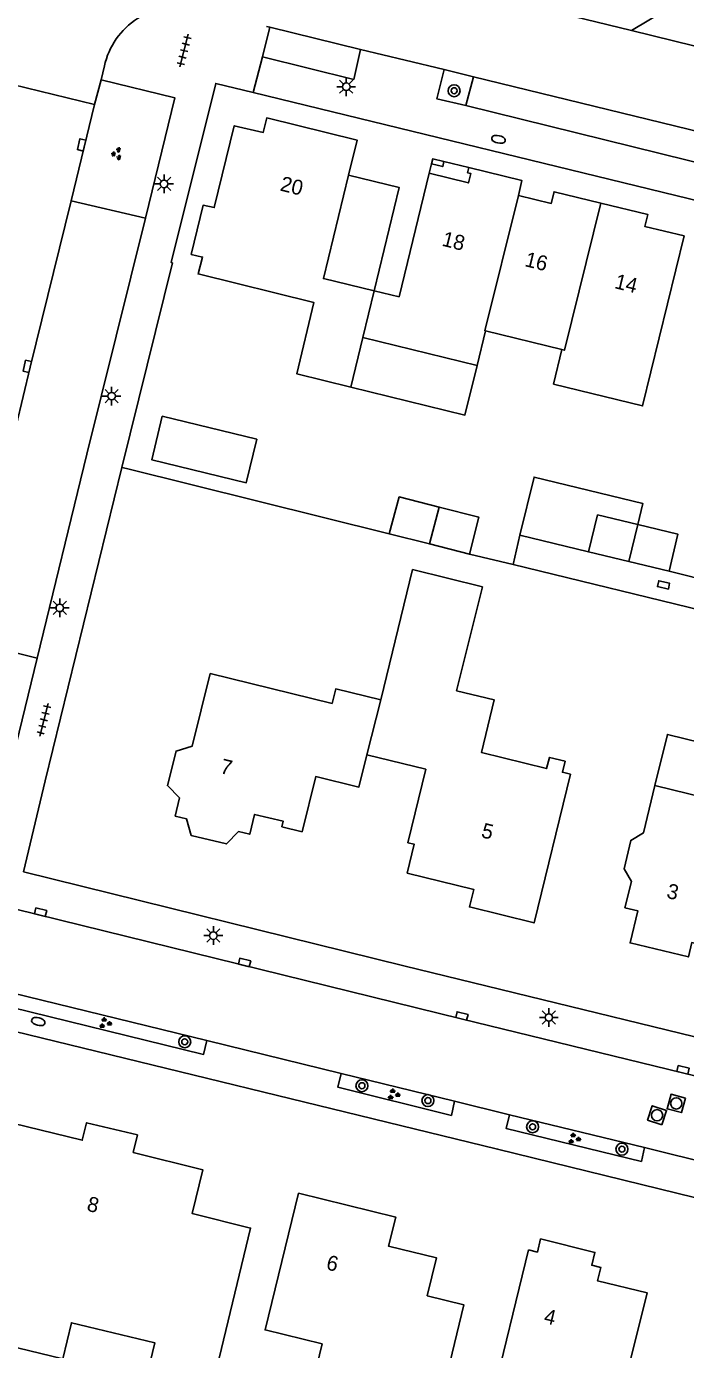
# Model space of a CAD drawing. Extents: x 125000 to 129004, y 397500 to 399008.
# Drawn here: x 126718 to 126762, y 398005.2 to 398093.6 of the extents above; entities that cross this region are included whole.
import ezdxf

# ---------------------------------------------------------------- set-up
doc = ezdxf.new("R2010")
doc.units = 0
for name, color, linetype in [('gg-afsc-erfafscheiding', 7, 'Continuous'), ('gg-afsc-muur', 7, 'Continuous'), ('gg-anno-huisnummerreeks BGT', 7, 'Continuous'), ('gg-bbg-bijgebouw', 7, 'Continuous'), ('gg-bbg-gedigitaliseerde bebouwing', 7, 'Continuous'), ('gg-bbg-hoofdgebouw', 7, 'Continuous'), ('gg-bbg-luifel en loopbrug', 7, 'Continuous'), ('gg-bbg-onder overbouw', 7, 'Continuous'), ('gg-bbg-pand overbouw', 7, 'Continuous'), ('gg-bbg-pilaar onder overbouw', 7, 'Continuous'), ('gg-bbg-pilaar pand', 7, 'Continuous'), ('gg-bbg-tussenscheiding', 7, 'Continuous'), ('gg-knt-verharding', 7, 'Continuous'), ('gg-knt-verharding nz', 7, 'Continuous'), ('gt-grn-weggrens', 7, 'Continuous'), ('gt-symb-boom', 7, 'Continuous'), ('gt-symb-brandkraan', 7, 'Continuous'), ('gt-symb-groenvak', 7, 'Continuous'), ('gt-symb-kolk', 7, 'Continuous'), ('gt-symb-kolk center center', 7, 'Continuous'), ('gt-symb-lichtmast', 7, 'Continuous'), ('gt-symb-rioolschacht', 7, 'Continuous'), ('gt-symb-tegel verharding', 7, 'Continuous')]:
    doc.layers.add(name, color=color, linetype=linetype)

# ---------------------------------------------------------------- blocks, each defined once
blk = doc.blocks.new('gt0-LMAST')
at = {"layer": 'gt-symb-lichtmast'}
for p, q in [((-0.182, 0.173), (-0.447, 0.438)), ((-0.005, 0.246), (-0.005, 0.621)), ((0.172, 0.173), (0.437, 0.438)), ((-0.255, -0.004), (-0.63, -0.004)), ((-0.182, -0.181), (-0.447, -0.446)), ((-0.005, -0.254), (-0.005, -0.629)), ((0.437, -0.446), (0.172, -0.181)), ((0.245, -0.004), (0.62, -0.004))]:
    blk.add_line(p, q, dxfattribs=at)
blk.add_circle((-0.005, -0.004), 0.25, dxfattribs=at)
blk = doc.blocks.new('gt0-TEG1')
at = {"layer": 'gt-symb-tegel verharding'}
for p, q in [((-1.125, 0), (1.125, 0)), ((-0.9, -0.25), (-0.9, 0.25)), ((-0.45, -0.25), (-0.45, 0.25)), ((0, -0.25), (0, 0.25)), ((0.45, -0.25), (0.45, 0.25)), ((0.9, -0.25), (0.9, 0.25))]:
    blk.add_line(p, q, dxfattribs=at)
blk = doc.blocks.new('gt0-BOOM')
at = {"layer": 'gt-symb-boom'}
for radius in [0.4, 0.2]:
    blk.add_circle((0, 0), radius, dxfattribs=at)
blk = doc.blocks.new('gt0-BR')
at = {"layer": 'gt-symb-brandkraan'}
for centre, radius, start, end in [((-0.244, 0), 0.206, 107.56694, 252.43307), ((0.599, -2.664), 3, 106.89205, 107.56694), ((0, -0.691), 0.938, 73.10799, 106.89205), ((-0.599, -2.664), 3, 72.43309, 73.10799), ((0.244, 0), 0.206, 287.56695, 72.43309), ((0.599, 2.664), 3, 252.43307, 253.10797), ((0, 0.691), 0.938, 253.10797, 286.89206), ((-0.599, 2.664), 3, 286.89206, 287.56695)]:
    blk.add_arc(centre, radius, start, end, dxfattribs=at)
blk = doc.blocks.new('gt0-GRVAK')
at = {"layer": 'gt-symb-groenvak'}
for p, q in [((-0.11, 0.189), (-0.228, 0.24)), ((-0.182, 0.153), (0.088, 0.153)), ((-0.091, 0.211), (-0.156, 0.322)), ((-0.047, 0.214), (-0.047, 0.393)), ((-0.004, 0.211), (0.061, 0.322)), ((0.015, 0.189), (0.133, 0.24)), ((0.262, -0.052), (0.197, 0.059)), ((0.305, -0.049), (0.305, 0.13)), ((0.349, -0.052), (0.414, 0.059)), ((-0.245, -0.228), (-0.363, -0.177)), ((-0.318, -0.264), (-0.047, -0.264)), ((-0.226, -0.206), (-0.291, -0.095)), ((-0.183, -0.203), (-0.183, -0.024)), ((-0.139, -0.206), (-0.074, -0.095)), ((-0.12, -0.228), (-0.002, -0.177)), ((0.243, -0.074), (0.125, -0.023)), ((0.17, -0.11), (0.441, -0.11)), ((0.368, -0.074), (0.486, -0.023))]:
    blk.add_line(p, q, dxfattribs=at)
blk = doc.blocks.new('gt0-KOLK')
at = {"layer": 'gt-symb-kolk'}
blk.add_lwpolyline([(0, 0), (0.375, 0), (0.375, 0.4), (-0.375, 0.4), (-0.375, 0), (0, 0)], dxfattribs=at)
blk = doc.blocks.new('gt0-KOLKCC')
at = {"layer": 'gt-symb-kolk center center'}
blk.add_lwpolyline([(-0.375, 0.2), (0.375, 0.2), (0.375, -0.2), (-0.375, -0.2)], close=True, dxfattribs=at)
blk = doc.blocks.new('gt0-RS')
at = {"layer": 'gt-symb-rioolschacht'}
blk.add_lwpolyline([(-0.5, -0.5), (0.5, -0.5), (0.5, 0.5), (-0.5, 0.5)], close=True, dxfattribs=at)
blk.add_circle((0, 0), 0.375, dxfattribs=at)

msp = doc.modelspace()

# ---------------------------------------------------------------- linework, layer by layer
at = {"layer": 'gg-afsc-erfafscheiding'}
for p, q in [((126724.351, 398064.121), (126719.221, 398043.177)), ((126742.224, 398059.684), (126724.663, 398064.05)), ((126750.494, 398057.621), (126750.952, 398059.587)), ((126747.589, 398058.33), (126750.494, 398057.621)), ((126760.922, 398057.186), (126768.349, 398055.337))]:
    msp.add_line(p, q, dxfattribs=at)
at = {"layer": 'gg-afsc-muur'}
for p, q in [((126727.738, 398077.785), (126724.351, 398064.121)), ((126724.351, 398064.121), (126724.663, 398064.05))]:
    msp.add_line(p, q, dxfattribs=at)
at = {"layer": 'gg-bbg-bijgebouw'}
for p, q in [((126742.224, 398059.684), (126744.907, 398059.007)), ((126744.907, 398059.007), (126747.589, 398058.33)), ((126755.532, 398058.478), (126758.227, 398057.832)), ((126758.227, 398057.832), (126760.922, 398057.186))]:
    msp.add_line(p, q, dxfattribs=at)
for points in [[(126733.358, 398066.01), (126727.052, 398067.534), (126726.357, 398064.622), (126732.663, 398063.097), (126733.358, 398066.01)], [(126745.547, 398061.47), (126742.882, 398062.147), (126742.224, 398059.684)], [(126747.589, 398058.33), (126748.211, 398060.792), (126745.547, 398061.47)], [(126758.83, 398060.296), (126756.148, 398060.945), (126755.532, 398058.478)], [(126760.922, 398057.186), (126761.512, 398059.646), (126758.83, 398060.296)]]:
    msp.add_lwpolyline(points, dxfattribs=at)
at = {"layer": 'gg-bbg-gedigitaliseerde bebouwing'}
msp.add_lwpolyline([(126744.727, 398002.6), (126743.485, 397997.447), (126736.193, 397999.205), (126737.725, 398005.556)], dxfattribs=at)
at = {"layer": 'gg-bbg-hoofdgebouw'}
for p, q in [((126744.89, 398083.768), (126742.883, 398075.504)), ((126741.212, 398075.91), (126740.455, 398072.798)), ((126741.212, 398075.91), (126742.883, 398075.504)), ((126740.455, 398072.798), (126739.648, 398069.477)), ((126740.455, 398072.798), (126748.087, 398070.933)), ((126748.087, 398070.933), (126748.653, 398073.243)), ((126748.653, 398073.243), (126753.748, 398071.993)), ((126753.748, 398071.993), (126753.196, 398069.678))]:
    msp.add_line(p, q, dxfattribs=at)
for points in [[(126739.648, 398069.477), (126736.034, 398070.376), (126737.184, 398075.133), (126729.447, 398077.043), (126729.74, 398078.17), (126728.981, 398078.352), (126729.773, 398081.639), (126730.522, 398081.476), (126731.862, 398086.947), (126733.794, 398086.503), (126734.03, 398087.464), (126740.069, 398085.985), (126739.497, 398083.634)], [(126750.86, 398082.296), (126751.091, 398083.279), (126747.537, 398084.149)], [(126739.497, 398083.634), (126737.82, 398076.734), (126741.212, 398075.91)], [(126756.37, 398081.772), (126753.235, 398082.538), (126753.045, 398081.761), (126750.86, 398082.296)], [(126753.196, 398069.678), (126759.155, 398068.227), (126761.921, 398079.582), (126759.3, 398080.222), (126759.504, 398081.005), (126756.37, 398081.772)], [(126741.651, 398048.586), (126743.778, 398057.295), (126748.446, 398056.134), (126746.719, 398049.191), (126749.237, 398048.587), (126748.392, 398045.066), (126752.739, 398043.992), (126752.921, 398044.74), (126753.97, 398044.484), (126753.79, 398043.746), (126754.324, 398043.615), (126751.898, 398033.677), (126747.58, 398034.756), (126747.871, 398035.92), (126743.42, 398037.013), (126743.893, 398038.936), (126743.466, 398039.041), (126744.657, 398043.953), (126740.716, 398044.909)], [(126759.972, 398042.859), (126759.202, 398039.699), (126758.365, 398039.198), (126757.91, 398037.293), (126758.403, 398036.445), (126757.974, 398034.691), (126758.839, 398034.48), (126758.313, 398032.341), (126762.21, 398031.407), (126762.441, 398032.37), (126766.753, 398031.297), (126768.875, 398039.997), (126772.277, 398039.167), (126775.303, 398051.571), (126771.055, 398052.607), (126769.034, 398044.256), (126766.363, 398044.913)], [(126730.245, 398050.341), (126729.047, 398045.496), (126727.967, 398045.166), (126727.392, 398042.853), (126728.198, 398042.03), (126727.915, 398040.824), (126728.665, 398040.647), (126728.987, 398039.534), (126731.335, 398038.965), (126732.145, 398039.783), (126732.894, 398039.602), (126733.216, 398040.933), (126735.131, 398040.47), (126735.04, 398040.111), (126736.406, 398039.766)], [(126741.651, 398048.586), (126738.638, 398049.321), (126738.4, 398048.349), (126730.245, 398050.341)], [(126736.406, 398039.766), (126737.303, 398043.465), (126740.196, 398042.763), (126740.716, 398044.909)], [(126766.363, 398044.913), (126765.522, 398041.495), (126759.972, 398042.859)], [(126720.396, 398004.551), (126713.594, 398006.203), (126714.661, 398010.595), (126713.699, 398010.829), (126714.809, 398015.395), (126715.78, 398015.159), (126717.031, 398020.309), (126721.7, 398019.166), (126721.985, 398020.331), (126725.392, 398019.515), (126725.113, 398018.348), (126729.767, 398017.181), (126729.037, 398014.271), (126732.956, 398013.288), (126729.653, 397999.601)], [(126737.725, 398005.556), (126733.918, 398006.483), (126736.143, 398015.621)], [(126736.143, 398015.621), (126742.653, 398014.025), (126742.177, 398012.082), (126745.382, 398011.296), (126744.762, 398008.771), (126747.202, 398008.175), (126745.796, 398002.342), (126744.727, 398002.6)], [(126751.516, 398011.834), (126752.117, 398011.691), (126752.333, 398012.564), (126755.965, 398011.667), (126755.757, 398010.808), (126756.367, 398010.65), (126756.138, 398009.767), (126759.457, 398008.975), (126757.897, 398002.709), (126761.037, 398001.918), (126759.558, 397995.85), (126756.293, 397996.646)], [(126753.117, 398000.508), (126748.998, 398001.513), (126751.516, 398011.834)], [(126725.645, 398001.835), (126726.56, 398005.625), (126720.98, 398006.971), (126720.396, 398004.551)]]:
    msp.add_lwpolyline(points, dxfattribs=at)
at = {"layer": 'gg-bbg-luifel en loopbrug'}
msp.add_line((126750.952, 398059.587), (126755.532, 398058.478), dxfattribs=at)
for points in [[(126741.212, 398075.91), (126742.889, 398082.809), (126739.497, 398083.634)], [(126739.648, 398069.477), (126747.275, 398067.612), (126748.087, 398070.933)], [(126750.952, 398059.587), (126751.902, 398063.473), (126759.172, 398061.695), (126758.83, 398060.296)], [(126766.363, 398044.913), (126760.812, 398046.277), (126759.972, 398042.859)]]:
    msp.add_lwpolyline(points, dxfattribs=at)
at = {"layer": 'gg-bbg-onder overbouw'}
msp.add_lwpolyline([(126747.537, 398084.149), (126747.454, 398083.809), (126747.667, 398083.757), (126747.513, 398083.125), (126744.89, 398083.768)], dxfattribs=at)
at = {"layer": 'gg-bbg-pand overbouw'}
for p, q in [((126745.053, 398084.396), (126744.89, 398083.768)), ((126747.537, 398084.149), (126745.872, 398084.551))]:
    msp.add_line(p, q, dxfattribs=at)
at = {"layer": 'gg-bbg-pilaar onder overbouw'}
msp.add_lwpolyline([(126745.872, 398084.551), (126745.793, 398084.22), (126745.053, 398084.396)], dxfattribs=at)
at = {"layer": 'gg-bbg-pilaar pand'}
msp.add_lwpolyline([(126745.872, 398084.551), (126745.132, 398084.727), (126745.053, 398084.396)], dxfattribs=at)
at = {"layer": 'gg-bbg-tussenscheiding'}
for p, q in [((126745.547, 398061.47), (126744.907, 398059.007)), ((126758.83, 398060.296), (126758.227, 398057.832)), ((126741.651, 398048.586), (126740.716, 398044.909))]:
    msp.add_line(p, q, dxfattribs=at)
for points in [[(126750.86, 398082.296), (126748.608, 398073.254), (126748.653, 398073.243)], [(126756.37, 398081.772), (126753.923, 398071.95), (126753.748, 398071.993)]]:
    msp.add_lwpolyline(points, dxfattribs=at)
at = {"layer": 'gg-knt-verharding'}
for p, q in [((126735.358, 398098.924), (126758.403, 398093.318)), ((126734.239, 398093.535), (126733.748, 398091.557)), ((126734.239, 398093.535), (126734.018, 398093.587)), ((126723.18, 398090.939), (126722.958, 398090.004)), ((126747.861, 398090.221), (126745.893, 398090.697)), ((126747.338, 398088.306), (126747.861, 398090.221)), ((126717.043, 398089.696), (126722.53, 398088.376)), ((126722.53, 398088.376), (126722.958, 398090.004)), ((126793.729, 398074.385), (126733.12, 398089.164)), ((126720.965, 398081.932), (126722.53, 398088.376)), ((126770.952, 398082.476), (126747.338, 398088.306)), ((126720.965, 398081.932), (126725.917, 398080.769)), ((126725.917, 398080.769), (126722.008, 398065.01)), ((126718.691, 398051.362), (126722.008, 398065.01)), ((126784.359, 398049.406), (126750.494, 398057.621)), ((126718.691, 398051.362), (126713.833, 398052.568)), ((126719.221, 398043.177), (126717.775, 398037.102)), ((126715.845, 398029.298), (126730.03, 398025.818)), ((126738.995, 398023.617), (126746.591, 398021.774)), ((126750.257, 398020.866), (126759.287, 398018.68))]:
    msp.add_line(p, q, dxfattribs=at)
for points in [[(126758.403, 398093.318), (126763.876, 398096.595), (126764.867, 398100.565)], [(126733.748, 398091.557), (126739.844, 398090.046), (126740.308, 398092.04)], [(126740.308, 398092.04), (126743.277, 398091.338), (126745.893, 398090.697)], [(126745.893, 398090.697), (126745.401, 398088.734), (126747.338, 398088.306)], [(126722.958, 398090.004), (126727.882, 398088.813), (126725.917, 398080.769)], [(126733.12, 398089.164), (126730.619, 398089.774), (126727.642, 398077.809), (126727.738, 398077.785)], [(126711.777, 398044.356), (126716.687, 398043.14), (126718.691, 398051.362)], [(126784.325, 398020.868), (126771.867, 398023.816), (126743.186, 398030.825), (126717.775, 398037.102)], [(126730.03, 398025.818), (126729.814, 398024.891), (126715.627, 398028.371)], [(126715.271, 398026.901), (126749.46, 398018.571), (126781.875, 398010.612)], [(126746.591, 398021.774), (126746.375, 398020.825), (126738.789, 398022.702), (126738.995, 398023.617)], [(126759.287, 398018.68), (126759.076, 398017.747), (126750.043, 398019.936), (126750.257, 398020.866)]]:
    msp.add_lwpolyline(points, dxfattribs=at)
msp.add_arc((126728.098, 398089.856), 5.035, 77.14318, 167.57789, dxfattribs=at)
at = {"layer": 'gg-knt-verharding nz'}
for p, q in [((126734.239, 398093.535), (126740.308, 398092.04)), ((126771.445, 398084.449), (126747.861, 398090.221)), ((126738.995, 398023.617), (126730.03, 398025.818)), ((126750.257, 398020.866), (126746.591, 398021.774)), ((126765.402, 398017.158), (126759.287, 398018.68))]:
    msp.add_line(p, q, dxfattribs=at)
for points in [[(126717.284, 398066.896), (126718.219, 398070.821), (126720.965, 398081.932)], [(126717.167, 398034.623), (126747.024, 398027.274), (126761.81, 398023.667), (126776.496, 398020.114), (126785.268, 398017.943)]]:
    msp.add_lwpolyline(points, dxfattribs=at)
at = {"layer": 'gt-grn-weggrens'}
for p, q in [((126758.403, 398093.318), (126770.567, 398090.327)), ((126733.12, 398089.164), (126733.748, 398091.557))]:
    msp.add_line(p, q, dxfattribs=at)

# ---------------------------------------------------------------- block references
at = {"layer": 'gt-symb-boom'}
for p in [(126746.556, 398089.287), (126728.549, 398025.739), (126740.395, 398022.806), (126744.807, 398021.807), (126751.801, 398020.06), (126757.773, 398018.565)]:
    msp.add_blockref('gt0-BOOM', p, dxfattribs=at)
at = {"layer": 'gt-symb-brandkraan'}
for p, rotation in [((126749.519, 398086.036), 167.93725397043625), ((126718.759, 398027.09), 165.81081984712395)]:
    msp.add_blockref('gt0-BR', p, dxfattribs=dict(at, rotation=rotation))
at = {"layer": 'gt-symb-groenvak', "rotation": 75.75525752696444}
msp.add_blockref('gt0-GRVAK', (126724.02, 398085.045), dxfattribs=at)
at = {"layer": 'gt-symb-groenvak'}
for p in [(126723.218, 398026.982), (126742.495, 398022.223), (126754.563, 398019.264)]:
    msp.add_blockref('gt0-GRVAK', p, dxfattribs=at)
at = {"layer": 'gt-symb-kolk'}
for p, rotation in [((126721.85, 398085.622), 76.5198737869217), ((126718.219, 398070.821), 76.58892815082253), ((126718.867, 398034.204), -13.827795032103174), ((126732.498, 398030.845), -13.827795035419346), ((126747.024, 398027.274), -13.82779503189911), ((126761.81, 398023.667), -13.702889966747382)]:
    msp.add_blockref('gt0-KOLK', p, dxfattribs=dict(at, rotation=rotation))
at = {"layer": 'gt-symb-kolk center center', "rotation": 167.46497664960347}
msp.add_blockref('gt0-KOLKCC', (126760.55, 398056.268), dxfattribs=at)
at = {"layer": 'gt-symb-lichtmast'}
for p in [(126739.351, 398089.558), (126727.173, 398083.062), (126723.67, 398068.885), (126720.203, 398054.733), (126730.467, 398032.838), (126752.888, 398027.366)]:
    msp.add_blockref('gt0-LMAST', p, dxfattribs=at)
at = {"layer": 'gt-symb-rioolschacht'}
for p, rotation in [((126761.401, 398021.621), 164.69967555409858), ((126760.119, 398020.831), 71.81873102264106)]:
    msp.add_blockref('gt0-RS', p, dxfattribs=dict(at, rotation=rotation))
at = {"layer": 'gt-symb-tegel verharding'}
for p, rotation in [((126728.509, 398091.964), 75.7552575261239), ((126719.141, 398047.255), 75.93596328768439)]:
    msp.add_blockref('gt0-TEG1', p, dxfattribs=dict(at, rotation=rotation))

# ---------------------------------------------------------------- texts
at = {"layer": 'gg-anno-huisnummerreeks BGT'}
for s, rotation, p in [('20', 346.2, (126734.868, 398082.625)), ('18', 346.2, (126745.686, 398078.939)), ('16', 346.2, (126751.219, 398077.575)), ('14', 346.2, (126757.221, 398076.102)), ('7', 346.2, (126730.862, 398043.705)), ('5', 346.2, (126748.315, 398039.415)), ('3', 346.5, (126760.699, 398035.369)), ('8', 346.2, (126721.949, 398014.467)), ('6', 346.2, (126737.95, 398010.545)), ('4', 346.3, (126752.497, 398006.962))]:
    msp.add_text(s, height=1, rotation=rotation, dxfattribs=at).set_placement(p)

doc.saveas('drawing.dxf')
